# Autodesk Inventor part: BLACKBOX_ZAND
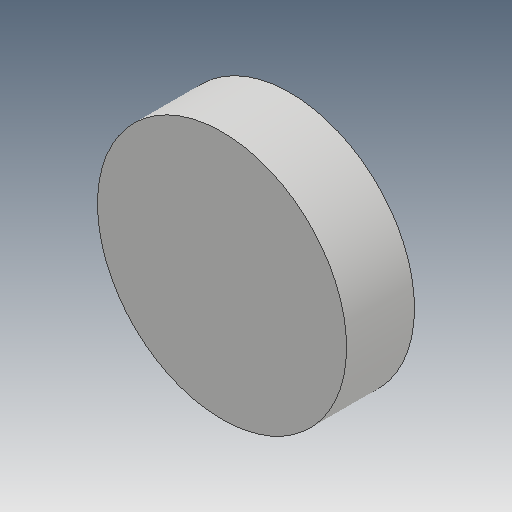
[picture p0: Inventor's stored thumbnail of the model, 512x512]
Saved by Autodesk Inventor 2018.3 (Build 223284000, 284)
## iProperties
Created: 2019-01
Part Number: BLACKBOX_ZAND
Material: Generisch
Document SubType Name: Modeling
Designer: zand
Density: 1 g/cm^3
Appearance: Vorgabe
Mass: 285.1 g
Surface Area: 293.739 cm^2
Volume: 285.1 cm^3
Author: zand
Revision Number: 2LAST_VERSION
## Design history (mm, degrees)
feature "Basis1"
node "Volumenkörper1"
